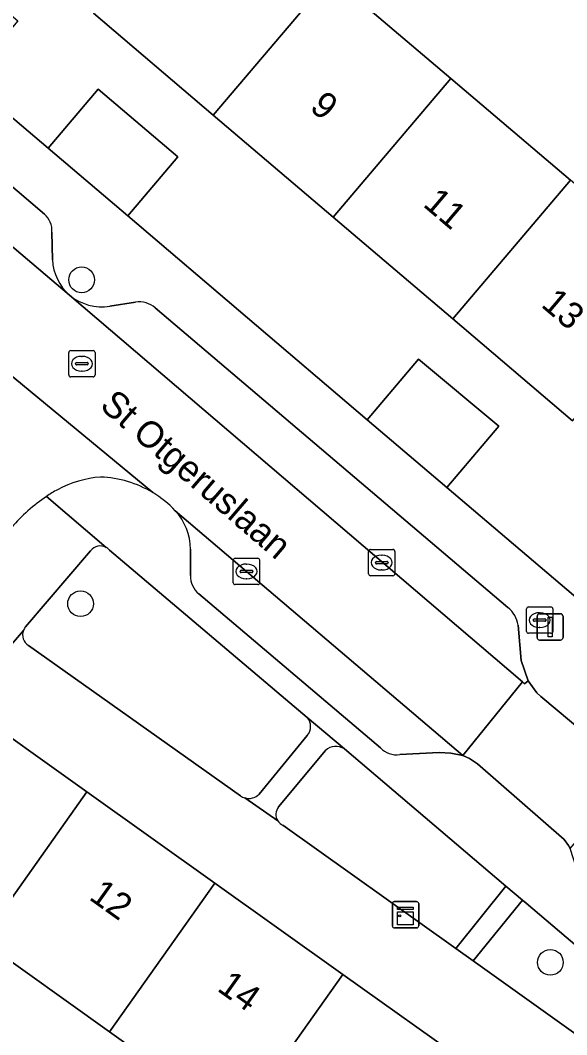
# Model space of a CAD drawing. Extents: x 162523 to 163266, y 381230 to 382050.
# Drawn here: x 163135.06 to 163155.81, y 381611.91 to 381650.41 of the extents above; entities that cross this region are included whole.
import ezdxf

# ---------------------------------------------------------------- set-up
doc = ezdxf.new("R2010")
doc.units = 0
for name, color, linetype in [('IMGEO_Boom', 7, 'Continuous'), ('IMGEO_Brandkraan', 7, 'Continuous'), ('IMGEO_Erf', 7, 'Continuous'), ('IMGEO_Groenvoorziening', 7, 'Continuous'), ('IMGEO_Kast', 7, 'Continuous'), ('IMGEO_Kolk', 7, 'Continuous'), ('IMGEO_Lichtmast', 7, 'Continuous'), ('IMGEO_Openbare_ruimte_label', 7, 'Continuous'), ('IMGEO_Pand', 7, 'Continuous'), ('IMGEO_Pand_nummerreeks', 7, 'Continuous'), ('IMGEO_Parkeervlak_open', 7, 'Continuous'), ('IMGEO_Rijbaan_lokaal_open', 7, 'Continuous'), ('IMGEO_Rioolput', 7, 'Continuous'), ('IMGEO_Voetpad_open', 7, 'Continuous')]:
    doc.layers.add(name, color=color, linetype=linetype)

msp = doc.modelspace()

# ---------------------------------------------------------------- linework, layer by layer
at = {"layer": 'IMGEO_Boom'}
for centre in [(163137.387, 381640.561), (163137.345, 381628.27), (163155.192, 381614.657)]:
    msp.add_circle(centre, 0.489, dxfattribs=at)
at = {"layer": 'IMGEO_Brandkraan'}
for p, q in [((163154.286, 381627.221), (163154.286, 381628.073)), ((163154.361, 381628.147), (163155.213, 381628.147)), ((163155.287, 381628.073), (163155.287, 381627.221)), ((163154.545, 381627.641), (163154.545, 381627.653)), ((163154.588, 381627.69), (163154.986, 381627.69)), ((163154.774, 381627.927), (163154.799, 381627.927)), ((163155.029, 381627.653), (163155.029, 381627.641)), ((163154.983, 381627.604), (163154.585, 381627.604)), ((163154.797, 381627.367), (163154.772, 381627.367)), ((163155.213, 381627.147), (163154.361, 381627.147))]:
    msp.add_line(p, q, dxfattribs=at)
for points in [[(163154.286, 381627.221), (163154.286, 381628.073)], [(163154.361, 381628.147), (163155.213, 381628.147)], [(163155.287, 381628.073), (163155.287, 381627.221)], [(163155.213, 381627.147), (163154.361, 381627.147)]]:
    msp.add_lwpolyline(points, dxfattribs=at)
for centre, radius, start, end in [((163154.363, 381628.071), 0.0765, 91.552, 178.448), ((163154.363, 381628.071), 0.0765, 91.552, 178.448), ((163155.211, 381628.071), 0.0765, 1.552, 88.448), ((163155.211, 381628.071), 0.0765, 1.552, 88.448), ((163154.585, 381627.65), 0.0403, 85.8775, 175.7526), ((163154.582, 381627.64), 0.0366, 178.938, 274.7102), ((163154.986, 381627.647), 0.043, 264.8664, 352.4533), ((163154.99, 381627.652), 0.0386, 1.7309, 96.639), ((163154.363, 381627.223), 0.0765, 181.552, 268.448), ((163154.363, 381627.223), 0.0765, 181.552, 268.448), ((163155.211, 381627.223), 0.0765, 271.552, 358.448), ((163155.211, 381627.223), 0.0765, 271.552, 358.448)]:
    msp.add_arc(centre, radius, start, end, dxfattribs=at)
for centre, major_axis, ratio, start_param, end_param in [((163154.773, 381627.647), (-0.387, 0.002), 0.722429, 4.712389, 7.853982), ((163154.798, 381627.647), (-0.39, 0.002), 0.717154, 1.570796, 4.712389)]:
    msp.add_ellipse(centre, major_axis=major_axis, ratio=ratio, start_param=start_param, end_param=end_param, dxfattribs=at)
at = {"layer": 'IMGEO_Erf'}
for points in [[(163156.896, 381663.899), (163153.342, 381666.904), (163155.023, 381668.883), (163153.012, 381670.586), (163151.33, 381668.605), (163144.22, 381674.618), (163145.907, 381676.604), (163143.897, 381678.307), (163142.209, 381676.319), (163138.519, 381679.439), (163128.484, 381667.696), (163133.212, 381663.677), (163137.76, 381659.81), (163142.309, 381655.943), (163144.491, 381658.512), (163149.039, 381654.645), (163146.857, 381652.076), (163151.406, 381648.209), (163155.954, 381644.343)], [(163131.859, 381653.027), (163134.967, 381650.388), (163133.063, 381648.145), (163136.111, 381645.555), (163138.017, 381647.799), (163141.043, 381645.229), (163139.137, 381642.985), (163148.238, 381635.254), (163150.184, 381637.546), (163153.232, 381635.003), (163151.263, 381632.684), (163157.339, 381627.523)], [(163156.035, 381635.214), (163151.486, 381639.08), (163146.937, 381642.946), (163142.387, 381646.812), (163137.838, 381650.678)], [(163157.898, 381598.17), (163153.034, 381601.633), (163148.171, 381605.095), (163143.308, 381608.557), (163138.445, 381612.02), (163133.581, 381615.483), (163132.053, 381613.331), (163127.282, 381616.72), (163128.814, 381618.877), (163132.827, 381624.514), (163130.978, 381625.9), (163115.401, 381607.592), (163156.805, 381578.185)]]:
    msp.add_lwpolyline(points, dxfattribs=at)
at = {"layer": 'IMGEO_Groenvoorziening'}
for points in [[(163138.017, 381647.799), (163136.111, 381645.555), (163139.137, 381642.985), (163141.043, 381645.229)], [(163150.184, 381637.546), (163148.238, 381635.254), (163151.263, 381632.684), (163153.232, 381635.003)], [(163154.269, 381616.898), (163154.131, 381617.015), (163152.264, 381614.71), (163159.357, 381609.653), (163160.679, 381611.466)]]:
    msp.add_lwpolyline(points, close=True, dxfattribs=at)
for points in [[(163137.726, 381630.282), (163135.259, 381627.393)], [(163145.957, 381623.954), (163138.441, 381630.305)], [(163135.372, 381626.689), (163143.427, 381620.979)], [(163144.128, 381621.046), (163145.956, 381623.266)], [(163146.644, 381622.703), (163144.871, 381620.554)], [(163145.035, 381619.863), (163151.596, 381615.186), (163153.507, 381617.545), (163147.367, 381622.758)]]:
    msp.add_lwpolyline(points, dxfattribs=at)
for centre, radius, start, end in [((163138.093, 381630.001), 0.462, 61.6955, 142.5741), ((163138.08, 381629.985), 0.483, 41.5533, 61.2355), ((163135.604, 381627.087), 0.461, 158.2365, 239.7775), ((163135.577, 381627.104), 0.43, 137.7876, 159.0447), ((163145.553, 381623.611), 0.53, 319.4627, 40.3707), ((163147.042, 381622.249), 0.604, 57.4731, 131.2273), ((163143.751, 381621.433), 0.558, 234.5391, 252.6231), ((163143.738, 381621.416), 0.538, 253.3595, 316.4902), ((163145.202, 381620.268), 0.438, 139.1367, 213.0179), ((163145.2, 381620.266), 0.435, 212.9428, 247.6718)]:
    msp.add_arc(centre, radius, start, end, dxfattribs=at)
at = {"layer": 'IMGEO_Kast'}
for p, q in [((163149.19, 381616.037), (163149.19, 381616.878)), ((163149.19, 381616.878), (163149.19, 381616.037)), ((163149.265, 381616.962), (163150.106, 381616.962)), ((163150.106, 381616.962), (163149.265, 381616.962)), ((163150.19, 381616.887), (163150.19, 381616.046)), ((163150.19, 381616.046), (163150.19, 381616.887)), ((163150.115, 381615.962), (163149.274, 381615.962)), ((163149.274, 381615.962), (163150.115, 381615.962))]:
    msp.add_line(p, q, dxfattribs=at)
for points in [[(163149.385, 381616.752), (163149.985, 381616.752), (163149.985, 381616.667), (163149.385, 381616.667), (163149.385, 381616.752)], [(163149.385, 381616.577), (163149.985, 381616.577), (163149.985, 381616.088), (163149.385, 381616.088), (163149.385, 381616.577)]]:
    msp.add_lwpolyline(points, dxfattribs=at)
msp.add_circle((163149.469, 381616.426), 0.0377, dxfattribs=at)
for centre, start, end in [((163149.268, 381616.884), 92.4484, 184.2845), ((163149.268, 381616.884), 92.4484, 184.2845), ((163150.112, 381616.884), 2.4484, 94.2845), ((163150.112, 381616.884), 2.4484, 94.2845), ((163149.268, 381616.04), 182.4484, 274.2845), ((163149.268, 381616.04), 182.4484, 274.2845), ((163150.112, 381616.04), 272.4484, 4.2845), ((163150.112, 381616.04), 272.4484, 4.2845)]:
    msp.add_arc(centre, 0.0779, start, end, dxfattribs=at)
at = {"layer": 'IMGEO_Kolk'}
for p, q in [((163148.36, 381630.33), (163149.212, 381630.33)), ((163143.223, 381629.994), (163144.075, 381629.994)), ((163148.285, 381629.404), (163148.285, 381630.256)), ((163148.773, 381630.11), (163148.798, 381630.11)), ((163149.286, 381630.256), (163149.286, 381629.404)), ((163143.148, 381629.068), (163143.148, 381629.92)), ((163143.636, 381629.774), (163143.661, 381629.774)), ((163144.149, 381629.92), (163144.149, 381629.068)), ((163148.544, 381629.824), (163148.544, 381629.836)), ((163148.982, 381629.787), (163148.584, 381629.787)), ((163148.587, 381629.873), (163148.985, 381629.873)), ((163148.796, 381629.55), (163148.771, 381629.55)), ((163149.028, 381629.836), (163149.028, 381629.824)), ((163143.407, 381629.488), (163143.407, 381629.5)), ((163143.845, 381629.451), (163143.447, 381629.451)), ((163143.45, 381629.537), (163143.848, 381629.537)), ((163143.659, 381629.214), (163143.634, 381629.214)), ((163143.891, 381629.5), (163143.891, 381629.488)), ((163149.212, 381629.33), (163148.36, 381629.33)), ((163144.075, 381628.994), (163143.223, 381628.994))]:
    msp.add_line(p, q, dxfattribs=at)
for points in [[(163148.36, 381630.33), (163149.212, 381630.33)], [(163143.223, 381629.994), (163144.075, 381629.994)], [(163148.285, 381629.404), (163148.285, 381630.256)], [(163149.286, 381630.256), (163149.286, 381629.404)], [(163143.148, 381629.068), (163143.148, 381629.92)], [(163144.149, 381629.92), (163144.149, 381629.068)], [(163149.212, 381629.33), (163148.36, 381629.33)], [(163144.075, 381628.994), (163143.223, 381628.994)]]:
    msp.add_lwpolyline(points, dxfattribs=at)
for centre, radius, start, end in [((163148.362, 381630.254), 0.0765, 91.552, 178.448), ((163148.362, 381630.254), 0.0765, 91.552, 178.448), ((163149.21, 381630.254), 0.0765, 1.552, 88.448), ((163149.21, 381630.254), 0.0765, 1.552, 88.448), ((163143.225, 381629.918), 0.0765, 91.552, 178.448), ((163143.225, 381629.918), 0.0765, 91.552, 178.448), ((163144.073, 381629.918), 0.0765, 1.552, 88.448), ((163144.073, 381629.918), 0.0765, 1.552, 88.448), ((163148.584, 381629.833), 0.0403, 85.8775, 175.7526), ((163148.581, 381629.823), 0.0366, 178.938, 274.7102), ((163148.985, 381629.83), 0.043, 264.8664, 352.4533), ((163148.989, 381629.835), 0.0386, 1.7309, 96.639), ((163143.447, 381629.497), 0.0403, 85.8775, 175.7526), ((163143.444, 381629.487), 0.0366, 178.938, 274.7102), ((163143.848, 381629.494), 0.043, 264.8664, 352.4533), ((163143.852, 381629.499), 0.0386, 1.7309, 96.639), ((163148.362, 381629.406), 0.0765, 181.552, 268.448), ((163148.362, 381629.406), 0.0765, 181.552, 268.448), ((163149.21, 381629.406), 0.0765, 271.552, 358.448), ((163149.21, 381629.406), 0.0765, 271.552, 358.448), ((163143.225, 381629.07), 0.0765, 181.552, 268.448), ((163143.225, 381629.07), 0.0765, 181.552, 268.448), ((163144.073, 381629.07), 0.0765, 271.552, 358.448), ((163144.073, 381629.07), 0.0765, 271.552, 358.448)]:
    msp.add_arc(centre, radius, start, end, dxfattribs=at)
for centre, major_axis, ratio, start_param, end_param in [((163148.772, 381629.83), (-0.387, 0.002), 0.722429, 4.712389, 7.853982), ((163148.797, 381629.83), (-0.39, 0.002), 0.717154, 1.570796, 4.712389), ((163143.635, 381629.494), (-0.387, 0.002), 0.722429, 4.712389, 7.853982), ((163143.66, 381629.494), (-0.39, 0.002), 0.717154, 1.570796, 4.712389)]:
    msp.add_ellipse(centre, major_axis=major_axis, ratio=ratio, start_param=start_param, end_param=end_param, dxfattribs=at)
at = {"layer": 'IMGEO_Lichtmast'}
for p, q in [((163154.685, 381626.989), (163154.685, 381627.789)), ((163154.685, 381627.789), (163154.685, 381626.989)), ((163154.785, 381627.889), (163155.575, 381627.889)), ((163155.575, 381627.889), (163154.785, 381627.889)), ((163155.675, 381627.789), (163155.675, 381626.989)), ((163155.675, 381626.989), (163155.675, 381627.789)), ((163155.575, 381626.889), (163154.785, 381626.889)), ((163154.785, 381626.889), (163155.575, 381626.889))]:
    msp.add_line(p, q, dxfattribs=at)
msp.add_lwpolyline([(163155.105, 381627.764), (163155.255, 381627.764), (163155.255, 381627.014), (163155.105, 381627.014), (163155.105, 381627.764)], dxfattribs=at)
for centre, start, end in [((163154.785, 381627.789), 90, 180), ((163154.785, 381627.789), 90, 180), ((163155.575, 381627.789), 0, 90), ((163155.575, 381627.789), 360, 90), ((163154.785, 381626.989), 180, 270), ((163154.785, 381626.989), 180, 270), ((163155.575, 381626.989), 270, 0), ((163155.575, 381626.989), 270, 0)]:
    msp.add_arc(centre, 0.1, start, end, dxfattribs=at)
at = {"layer": 'IMGEO_Pand'}
for points in [[(163146.857, 381652.076), (163149.039, 381654.645), (163144.491, 381658.512), (163142.309, 381655.943), (163137.838, 381650.678), (163142.387, 381646.812)], [(163142.387, 381646.812), (163146.937, 381642.946), (163151.406, 381648.209), (163146.857, 381652.076)], [(163146.937, 381642.946), (163151.486, 381639.08), (163155.954, 381644.343), (163151.406, 381648.209)], [(163162.834, 381643.222), (163160.518, 381645.191), (163158.186, 381642.446), (163155.954, 381644.343), (163151.486, 381639.08), (163156.035, 381635.214), (163160.503, 381640.476), (163162.699, 381643.063)], [(163133.581, 381615.483), (163137.588, 381621.124), (163132.827, 381624.514), (163128.814, 381618.877), (163127.282, 381616.72), (163132.053, 381613.331)], [(163142.452, 381617.661), (163137.588, 381621.124), (163133.581, 381615.483), (163138.445, 381612.02)], [(163142.452, 381617.661), (163138.445, 381612.02), (163143.308, 381608.557), (163147.315, 381614.199)], [(163147.315, 381614.199), (163143.308, 381608.557), (163148.171, 381605.095), (163152.178, 381610.736)]]:
    msp.add_lwpolyline(points, close=True, dxfattribs=at)
at = {"layer": 'IMGEO_Parkeervlak_open'}
for points in [[(163117.413, 381656.545), (163136.925, 381639.983)], [(163135.974, 381643.057), (163120.655, 381656.119)], [(163136.277, 381641.324), (163136.259, 381642.37)], [(163136.925, 381639.983), (163154.129, 381625.302), (163154.207, 381625.235), (163154.343, 381625.343), (163154.089, 381626.115), (163153.965, 381627.453)], [(163139.438, 381639.719), (163138.456, 381639.559)], [(163153.579, 381628.124), (163140.185, 381639.494)], [(163149.469, 381622.545), (163150.97, 381622.618), (163151.417, 381622.599), (163151.866, 381622.506), (163140.942, 381631.797)], [(163141.524, 381630.345), (163141.516, 381629.337)], [(163141.841, 381628.646), (163148.742, 381622.799)]]:
    msp.add_lwpolyline(points, dxfattribs=at)
for centre, radius, start, end in [((163135.424, 381642.426), 0.837, 356.1405, 48.9215), ((163138.172, 381641.413), 1.897, 182.6756, 228.9061), ((163138.16, 381641.465), 1.929, 230.2, 278.8406), ((163139.569, 381638.801), 0.927, 48.3543, 98.1206), ((163139.366, 381630.323), 2.158, 0.5963, 43.0882), ((163142.418, 381629.339), 0.902, 180.156, 230.2222), ((163152.95, 381627.315), 1.025, 7.7181, 52.1021), ((163149.346, 381623.361), 0.825, 222.9237, 278.5594)]:
    msp.add_arc(centre, radius, start, end, dxfattribs=at)
at = {"layer": 'IMGEO_Rijbaan_lokaal_open'}
for points in [[(163117.413, 381656.545), (163116.999, 381656.899), (163114.738, 381654.244), (163115.08, 381653.95), (163132.09, 381639.443), (163131.922, 381639.226), (163140.086, 381632.485)], [(163140.942, 381631.797), (163151.866, 381622.506), (163154.129, 381625.302), (163136.925, 381639.983), (163117.413, 381656.545)], [(163140.086, 381632.485), (163131.922, 381639.226)]]:
    msp.add_lwpolyline(points, dxfattribs=at)
msp.add_lwpolyline([(163155.947, 381618.976), (163158.315, 381621.734), (163158.107, 381621.91), (163158.194, 381622.012), (163157.973, 381622.156), (163157.707, 381622.339), (163154.829, 381624.748), (163154.677, 381624.892), (163154.343, 381625.343), (163154.207, 381625.235), (163154.129, 381625.302), (163151.866, 381622.506), (163152.117, 381622.4), (163152.423, 381622.195), (163155.719, 381619.322), (163155.878, 381619.093)], close=True, dxfattribs=at)
for centre, radius, start, end in [((163138.433, 381628.916), 4.173, 94.4676, 118.1225), ((163137.949, 381628.947), 4.133, 58.8749, 87.801), ((163139.757, 381626.806), 6.66, 123.7686, 139.1241), ((163139.511, 381627.21), 6.189, 119.4791, 123.9535), ((163137.974, 381628.981), 4.092, 43.4974, 58.9222)]:
    msp.add_arc(centre, radius, start, end, dxfattribs=at)
at = {"layer": 'IMGEO_Rioolput'}
for p, q in [((163136.897, 381636.952), (163136.897, 381637.804)), ((163136.972, 381637.878), (163137.824, 381637.878)), ((163137.385, 381637.658), (163137.41, 381637.658)), ((163137.898, 381637.804), (163137.898, 381636.952)), ((163137.156, 381637.372), (163137.156, 381637.384)), ((163137.594, 381637.335), (163137.196, 381637.335)), ((163137.199, 381637.421), (163137.597, 381637.421)), ((163137.64, 381637.384), (163137.64, 381637.372)), ((163137.824, 381636.878), (163136.972, 381636.878)), ((163137.408, 381637.098), (163137.383, 381637.098))]:
    msp.add_line(p, q, dxfattribs=at)
for points in [[(163136.897, 381636.952), (163136.897, 381637.804)], [(163136.972, 381637.878), (163137.824, 381637.878)], [(163137.898, 381637.804), (163137.898, 381636.952)], [(163137.824, 381636.878), (163136.972, 381636.878)]]:
    msp.add_lwpolyline(points, dxfattribs=at)
for centre, radius, start, end in [((163136.974, 381637.802), 0.0765, 91.552, 178.448), ((163136.974, 381637.802), 0.0765, 91.552, 178.448), ((163137.822, 381637.802), 0.0765, 1.552, 88.448), ((163137.822, 381637.802), 0.0765, 1.552, 88.448), ((163137.196, 381637.381), 0.0403, 85.8775, 175.7526), ((163137.193, 381637.371), 0.0366, 178.938, 274.7102), ((163137.597, 381637.378), 0.043, 264.8664, 352.4533), ((163137.601, 381637.383), 0.0386, 1.7309, 96.639), ((163136.974, 381636.954), 0.0765, 181.552, 268.448), ((163136.974, 381636.954), 0.0765, 181.552, 268.448), ((163137.822, 381636.954), 0.0765, 271.552, 358.448), ((163137.822, 381636.954), 0.0765, 271.552, 358.448)]:
    msp.add_arc(centre, radius, start, end, dxfattribs=at)
for centre, major_axis, ratio, start_param, end_param in [((163137.384, 381637.378), (-0.387, 0.002), 0.722429, 4.712389, 7.853982), ((163137.409, 381637.378), (-0.39, 0.002), 0.717154, 1.570796, 4.712389)]:
    msp.add_ellipse(centre, major_axis=major_axis, ratio=ratio, start_param=start_param, end_param=end_param, dxfattribs=at)
at = {"layer": 'IMGEO_Voetpad_open'}
for points in [[(163159.568, 381625.629), (163157.339, 381627.523), (163151.263, 381632.684), (163148.238, 381635.254), (163139.137, 381642.985), (163136.111, 381645.555), (163133.063, 381648.145), (163127.011, 381653.286), (163123.962, 381655.875), (163120.755, 381658.6), (163119.655, 381659.534), (163118.125, 381660.834), (163117.58, 381661.297), (163106.497, 381670.706), (163101.218, 381675.181), (163100.456, 381675.828), (163098.283, 381673.302)], [(163120.655, 381656.119), (163135.974, 381643.057)], [(163136.259, 381642.37), (163136.277, 381641.324)], [(163138.456, 381639.559), (163139.438, 381639.719)], [(163140.185, 381639.494), (163153.579, 381628.124)], [(163138.312, 381630.408), (163136.055, 381632.343)], [(163136.055, 381632.343), (163138.312, 381630.408)], [(163141.516, 381629.337), (163141.524, 381630.345)], [(163135.259, 381627.393), (163137.726, 381630.282)], [(163138.441, 381630.305), (163145.957, 381623.954), (163147.367, 381622.758), (163153.507, 381617.545), (163154.131, 381617.015), (163154.269, 381616.898), (163160.679, 381611.466), (163161.38, 381610.903), (163169.583, 381603.926), (163170.16, 381604.607), (163156.665, 381616.044)], [(163148.742, 381622.799), (163141.841, 381628.646)], [(163114.48, 381606.51), (163115.401, 381607.592), (163130.978, 381625.9), (163132.827, 381624.514), (163135.176, 381627.258)], [(163135.176, 381627.258), (163132.827, 381624.514), (163137.588, 381621.124), (163142.452, 381617.661), (163147.315, 381614.199), (163152.178, 381610.736), (163157.042, 381607.274)], [(163153.965, 381627.453), (163154.089, 381626.115), (163154.343, 381625.343), (163154.677, 381624.892), (163154.829, 381624.748), (163157.707, 381622.339), (163157.973, 381622.156), (163158.194, 381622.012)], [(163143.427, 381620.979), (163135.372, 381626.689)], [(163147.367, 381622.758), (163145.957, 381623.954)], [(163145.956, 381623.266), (163144.128, 381621.046)], [(163144.871, 381620.554), (163146.644, 381622.703)], [(163156.339, 381616.731), (163156.204, 381618.189), (163155.947, 381618.976), (163155.878, 381619.093), (163155.719, 381619.322), (163152.423, 381622.195), (163152.117, 381622.4), (163151.866, 381622.506), (163151.417, 381622.599), (163150.97, 381622.618), (163149.469, 381622.545)], [(163144.835, 381620.029), (163143.584, 381620.901)], [(163143.584, 381620.901), (163144.835, 381620.029)], [(163168.783, 381602.886), (163160.118, 381609.122), (163159.357, 381609.653), (163152.264, 381614.71), (163151.596, 381615.186), (163145.035, 381619.863)]]:
    msp.add_lwpolyline(points, dxfattribs=at)
msp.add_lwpolyline([(163154.131, 381617.015), (163153.507, 381617.545), (163151.596, 381615.186), (163152.264, 381614.71)], close=True, dxfattribs=at)
for centre, radius, start, end in [((163135.424, 381642.426), 0.837, 356.1405, 48.9215), ((163138.172, 381641.413), 1.897, 182.6756, 228.9061), ((163138.16, 381641.465), 1.929, 230.2, 278.8406), ((163139.569, 381638.801), 0.927, 48.3543, 98.1206), ((163138.433, 381628.916), 4.173, 94.4676, 118.1225), ((163137.949, 381628.947), 4.133, 58.8749, 87.801), ((163139.757, 381626.806), 6.66, 123.7686, 139.1241), ((163139.511, 381627.21), 6.189, 119.4791, 123.9535), ((163137.974, 381628.981), 4.092, 43.4974, 58.9222), ((163139.366, 381630.323), 2.158, 0.5963, 43.0882), ((163138.093, 381630.001), 0.462, 61.6955, 142.5741), ((163138.08, 381629.985), 0.483, 41.5533, 61.2355), ((163142.418, 381629.339), 0.902, 180.156, 230.2222), ((163152.95, 381627.315), 1.025, 7.7181, 52.1021), ((163135.604, 381627.087), 0.461, 158.2365, 239.7775), ((163135.577, 381627.104), 0.43, 137.7876, 159.0447), ((163145.553, 381623.611), 0.53, 319.4627, 40.3707), ((163147.042, 381622.249), 0.604, 57.4731, 131.2273), ((163149.346, 381623.361), 0.825, 222.9237, 278.5594), ((163143.751, 381621.433), 0.558, 234.5391, 252.6231), ((163143.738, 381621.416), 0.538, 253.3595, 316.4902), ((163145.202, 381620.268), 0.438, 139.1367, 213.0179), ((163145.2, 381620.266), 0.435, 212.9428, 247.6718)]:
    msp.add_arc(centre, radius, start, end, dxfattribs=at)

# ---------------------------------------------------------------- texts
at = {"layer": 'IMGEO_Openbare_ruimte_label'}
msp.add_text('St Otgeruslaan', height=1, rotation=319.2993, dxfattribs=at).set_placement((163138.033, 381635.718))
at = {"layer": 'IMGEO_Pand_nummerreeks'}
for s, rotation, p in [('9', 319.642, (163146.007, 381647.044)), ('11', 319.642, (163150.315, 381643.382)), ('13', 319.6409, (163154.8, 381639.57)), ('12', 324.5501, (163137.624, 381617.072)), ('14', 324.5501, (163142.493, 381613.605))]:
    msp.add_text(s, height=1, rotation=rotation, dxfattribs=at).set_placement(p)

doc.saveas('drawing.dxf')
